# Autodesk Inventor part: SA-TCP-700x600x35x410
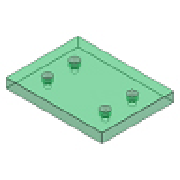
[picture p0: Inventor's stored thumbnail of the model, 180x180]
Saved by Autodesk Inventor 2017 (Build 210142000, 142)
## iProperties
Created: 2016-02
Part Number: SA-TCP-700x600x35x410
Material: S 55 C
Description: Top Clamping Plate
Document SubType Name: Modeling
Designer: Sandeep
Standard Revision: 1
Manufacturer: FUTABA
Language: en-US
Size Designation: 700x600x35x410
Categories: <MemberInstance><Categories><Category DisplayName="Mold" InternalName="349578f2-f4d4-4954-8c09-8e99297a61c0" Mnemonic="MOLD"><Category DisplayName="Mold Plates"
Density: 7.85 g/cm^3
Appearance: Clear - Green 1
IsCustomPart: 1
Author: Sandeep
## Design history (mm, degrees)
sketch "Sketch1"
  geometry: L1 (-300, 350)-(300, 350); L2 (300, 350)-(300, -350); L3 (300, -350)-(-300, -350); L4 (-300, -350)-(-300, 350); 3 further points
  constraints: 8 end point, 2 midpoint, 2 parallel, 1 horizontal, 1 horizontal alignment, 1 perpendicular, 1 vertical alignment
  dimensions: "d72" = 600 distance between parallel lines of L2 L4 (= W_); "d73" = 700 distance between parallel lines of L3 L1 (= L)
extrude "Extrusion1" new body sketch "Sketch1" distance "d20" = 35 (= H_); taper "d30" = 0 deg
feature "Sculpt1"
body "Solid1"
sketch "Sketch2"
  geometry: 2 further points
  dimensions: "d53" = 205 horizontal distance of point (0, 0) point (-205, 243) (= 0.5 x S1_W); "d54" = 243 vertical distance of point (0, 0) point (-205, 243) (= 0.5 x S1_L)
hole "Hole1" sketch "Sketch2" diameter "d55" = 18 (= S1_d1); stored, may be unused: countersink angle "d59" = 90 deg, drill point angle "d61" = 0 deg; dims "d56" = 6, "d57" = 26 (= S1_d2), "d58" = 17.5 (= S1_k), "d60" = 35 (= H_)
pattern_linear "Rectangular Pattern1" dims "d64" = 243 (computed from S1_L, Ns), "d67" = 410 (computed from S1_W, Nw)
chamfer "Chamfer1" distance "d68" = 0.5; stored, may be unused: second distance "d69" = 2, angle "d71" = 45 deg
feature "Surface1"
body "Srf1"
other parameters: "L" = 700 [user parameter; used in 1 equation term], "W_" = 600 [user parameter; used in 1 equation term], "H_" = 35 [user parameter; used in 2 equation terms], "S1_d1" = 18 [user parameter; used in 1 equation term], "S1_d2" = 26 [user parameter; used in 1 equation term], "S1_k" = 17.5 [user parameter; used in 1 equation term], "S1_L" = 486 [user parameter; used in 2 equation terms]
